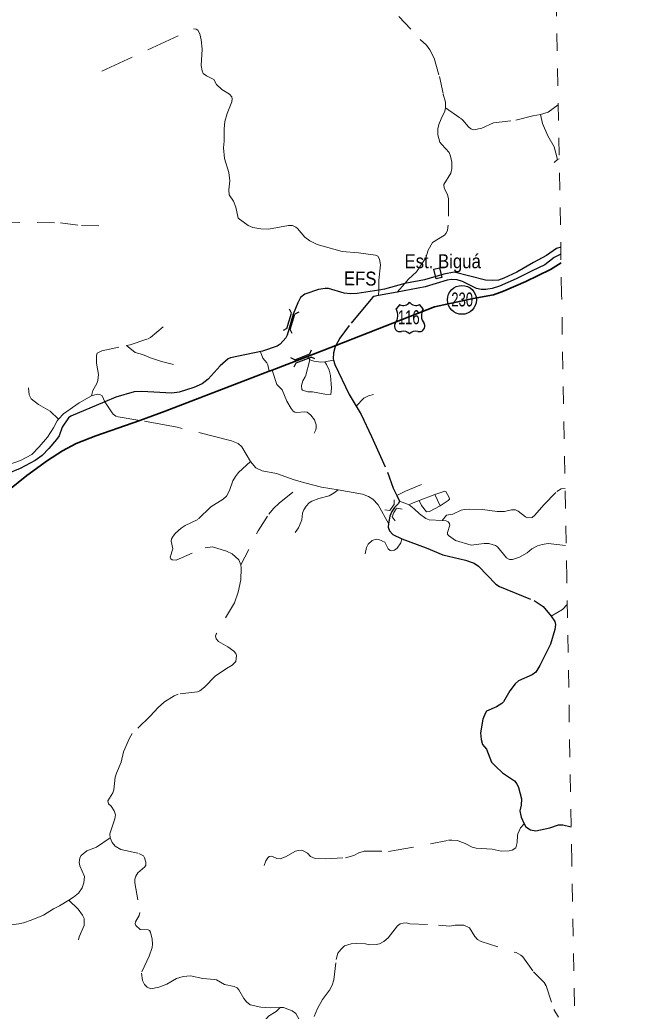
# Model space of a CAD drawing. Extents: x 220.8 to 246.7, y 7287.6 to 7315.8.
# Drawn here: x 243.16 to 246.65, y 7305.15 to 7310.84 of the extents above; entities that cross this region are included whole.
import ezdxf
from ezdxf.enums import TextEntityAlignment as Align

# ---------------------------------------------------------------- set-up
doc = ezdxf.new("R2010")
doc.units = 0
doc.header["$LTSCALE"] = 0.032
for name, pattern in [('DOTTED', [1.5, 0.3, -1.2]), ('LONG_DASHED', [7.5, 6, -1.5]), ('MEDIUM_DASHED', [4.5, 3, -1.5]), ('SHORT_DASHED', [2.7, 1.5, -1.2])]:
    doc.linetypes.add(name, pattern=pattern)
for name, color, linetype, lineweight in [('10', 7, 'Continuous', 25), ('11', 7, 'Continuous', 13), ('12', 7, 'Continuous', 25), ('13', 7, 'Continuous', 25), ('15', 7, 'Continuous', 25), ('2', 7, 'Continuous', 35), ('28', 7, 'Continuous', 25), ('35', 7, 'SHORT_DASHED', 13), ('4', 7, 'LONG_DASHED', 25), ('5', 7, 'LONG_DASHED', 13), ('6', 7, 'MEDIUM_DASHED', 13), ('7', 7, 'DOTTED', 13)]:
    doc.layers.add(name, color=color, linetype=linetype, lineweight=lineweight)
doc.layers.add('61', color=7, linetype='Continuous')

msp = doc.modelspace()

# ---------------------------------------------------------------- linework, layer by layer
at = {"layer": '10'}
for p, q in [((244.71, 7309.0644), (244.7373, 7309.1527)), ((244.7593, 7309.1644), (244.7373, 7309.1527)), ((244.6908, 7309.0703), (244.6687, 7309.0587)), ((244.7215, 7309.0424), (244.71, 7309.0644)), ((244.7359, 7308.8913), (244.7131, 7308.9014)), ((244.7332, 7308.8499), (244.7431, 7308.8727)), ((244.7431, 7308.8727), (244.8293, 7308.9061)), ((244.8522, 7308.8961), (244.8293, 7308.9061))]:
    msp.add_line(p, q, dxfattribs=at)
for points in [[(244.6908, 7309.0703), (244.7182, 7309.1586), (244.7065, 7309.1808)], [(244.7359, 7308.8913), (244.8221, 7308.9248), (244.8322, 7308.9477)]]:
    msp.add_lwpolyline(points, dxfattribs=at)
at = {"layer": '11'}
for points in [[(245.3067, 7308.0857), (245.3077, 7308.0596), (245.2986, 7308.05), (245.2811, 7308.0249), (245.2538, 7308.0278)], [(245.3536, 7308.0318), (245.3234, 7308.0384), (245.3188, 7308.0336), (245.3043, 7308.0127), (245.2949, 7307.9882), (245.3117, 7307.9649)]]:
    msp.add_lwpolyline(points, dxfattribs=at)
at = {"layer": '12'}
for p, q in [((245.3385, 7309.2082), (245.3176, 7309.1839)), ((245.4738, 7309.1841), (245.4528, 7309.2082))]:
    msp.add_line(p, q, dxfattribs=at)
for centre, radius, start, end in [((245.3593, 7309.2483), 0.0452, 242.5287, 323.4161), ((245.4319, 7309.2483), 0.0452, 216.5968, 297.4912), ((245.2544, 7309.1457), 0.0738, 320.9608, 31.1419), ((245.5368, 7309.1457), 0.0738, 148.687, 219.0536), ((245.3396, 7309.0841), 0.0316, 151.5003, 286.5066), ((245.4517, 7309.0841), 0.0316, 253.4942, 28.4996), ((245.3616, 7309.0124), 0.0433, 38.3472, 107.6219), ((245.4296, 7309.0124), 0.0433, 72.467, 141.6528)]:
    msp.add_arc(centre, radius, start, end, dxfattribs=at)
at = {"layer": '13'}
msp.add_circle((245.6962, 7309.235), 0.083, dxfattribs=at)
at = {"layer": '15'}
msp.add_lwpolyline([(246.2637, 7309.5375), (246.2398, 7309.5298), (246.1817, 7309.4896), (246.1065, 7309.4503), (246.0116, 7309.3947), (245.9373, 7309.3597), (245.9065, 7309.3486), (245.8741, 7309.346), (245.8322, 7309.3477), (245.6519, 7309.3939), (245.592, 7309.3828), (245.4818, 7309.3495), (245.369, 7309.3293), (245.2511, 7309.2965), (245.2179, 7309.2911), (245.0938, 7309.2708), (245.0562, 7309.27), (245.0195, 7309.2743), (244.9306, 7309.3007), (244.9101, 7309.3007), (244.8725, 7309.2948), (244.7939, 7309.2683), (244.7691, 7309.2478), (244.7529, 7309.2179), (244.7262, 7309.1519), (244.7011, 7309.064), (244.6933, 7309.0331), (244.6854, 7309.017), (244.652, 7308.9811), (244.6341, 7308.9683), (244.5503, 7308.9401), (244.3675, 7308.9025), (244.3538, 7308.8965), (244.3076, 7308.8555), (244.2384, 7308.7786), (244.2034, 7308.7521), (244.1572, 7308.7316), (244.0726, 7308.7051), (244.0299, 7308.6983), (243.8573, 7308.7085), (243.8146, 7308.7068), (243.7086, 7308.6761), (243.6456, 7308.6496), (243.4505, 7308.5675), (243.4368, 7308.5573), (243.4001, 7308.5043), (243.3822, 7308.4539), (243.3676, 7308.4317), (243.324, 7308.3804), (243.2847, 7308.3411), (243.2446, 7308.3112), (243.1583, 7308.265), (243.0839, 7308.236)], dxfattribs=at)
at = {"layer": '2'}
msp.add_lwpolyline([(242.9873, 7308.0568), (243.1979, 7308.2257), (243.316, 7308.311), (243.4026, 7308.3674), (243.4813, 7308.4094), (243.5941, 7308.4527), (243.8457, 7308.5424), (243.9917, 7308.5944), (244.5891, 7308.8254), (244.6053, 7308.8315), (244.7744, 7308.8953), (244.8086, 7308.9086), (244.9724, 7308.9729), (245.5386, 7309.1953), (245.7603, 7309.2426), (245.8771, 7309.2649), (245.9349, 7309.2845), (246.0634, 7309.3397), (246.2038, 7309.4092), (246.2653, 7309.4486)], dxfattribs=at)
at = {"layer": '28'}
msp.add_lwpolyline([(245.5668, 7309.4186), (245.5803, 7309.3632), (245.5473, 7309.3552), (245.5338, 7309.4106)], close=True, dxfattribs=at)
at = {"layer": '35'}
msp.add_lwpolyline([(246.6507, 7288.0853), (246.6212, 7289.7146), (246.5917, 7291.3439), (246.5622, 7292.9732), (246.5328, 7294.6024), (246.5034, 7296.2317), (246.4739, 7297.861), (246.4446, 7299.4903), (246.4152, 7301.1196), (246.3858, 7302.7489), (246.3565, 7304.3782), (246.3272, 7306.0075), (246.2979, 7307.6367), (246.2685, 7309.266), (246.2393, 7310.8953), (246.21, 7312.5246), (246.1808, 7314.1539), (246.1516, 7315.7832)], dxfattribs=at)
at = {"layer": '4'}
msp.add_lwpolyline([(246.2644, 7309.4984), (246.2261, 7309.4787), (246.1726, 7309.436), (246.0998, 7309.4011), (246.007, 7309.3567), (245.9117, 7309.3131), (245.8706, 7309.3003), (245.8325, 7309.2937), (245.8063, 7309.2937), (245.78, 7309.3003), (245.7, 7309.3397), (245.6685, 7309.3502), (245.637, 7309.3515), (245.6108, 7309.3488), (245.4848, 7309.3095), (245.325, 7309.2795), (245.2171, 7309.2593), (245.1909, 7309.2544), (245.1817, 7309.2491), (245.0492, 7309.0877), (244.9941, 7309.0143), (244.9724, 7308.9729), (244.9652, 7308.9592), (244.9587, 7308.9303), (244.9561, 7308.8962), (244.9582, 7308.8884), (244.9652, 7308.8634), (245.0479, 7308.6915), (245.0882, 7308.6245), (245.1174, 7308.576), (245.1765, 7308.4501), (245.2683, 7308.2441), (245.3011, 7308.1522), (245.322, 7308.1114), (245.3366, 7308.0774), (245.3313, 7308.0656), (245.3087, 7308.0418), (245.2927, 7308.0188), (245.2828, 7307.9928), (245.2737, 7307.9488), (245.2723, 7307.9292), (245.2801, 7307.9069), (245.2998, 7307.8859), (245.3513, 7307.8615), (245.4914, 7307.8098), (245.5858, 7307.7704), (245.7157, 7307.7389), (245.7656, 7307.7219), (245.7918, 7307.7048), (245.8916, 7307.6012), (245.9125, 7307.5867), (246.1107, 7307.5067), (246.1632, 7307.4726), (246.2088, 7307.4174), (246.2288, 7307.3873), (246.234, 7307.3689), (246.2301, 7307.3401), (246.2051, 7307.2561), (246.1435, 7307.1341), (246.1199, 7307.096), (246.1002, 7307.0803), (246.0214, 7307.0449), (246.0018, 7307.0291), (245.9716, 7306.9884), (245.9349, 7306.9255), (245.9244, 7306.915), (245.8955, 7306.8966), (245.8378, 7306.8704), (245.8299, 7306.8585), (245.8168, 7306.8257), (245.8023, 7306.7457), (245.8063, 7306.7077), (245.8141, 7306.6801), (245.8364, 7306.6525), (245.8666, 7306.5778), (245.8889, 7306.5541), (245.9293, 7306.5172), (245.9978, 7306.4702), (246.0115, 7306.4533), (246.0201, 7306.4321), (246.0385, 7306.3665), (246.0372, 7306.3311), (246.0293, 7306.2983), (246.0359, 7306.2616), (246.0541, 7306.2228), (246.0634, 7306.2064), (246.0897, 7306.1881), (246.1212, 7306.1828), (246.2012, 7306.2012), (246.2511, 7306.2169), (246.276, 7306.2169), (246.3236, 7306.2065)], dxfattribs=at)
at = {"layer": '5'}
for points in [[(243.6274, 7310.5486), (244.1537, 7310.7934), (244.1691, 7310.7912), (244.179, 7310.7846), (244.1901, 7310.7647), (244.1989, 7310.7294), (244.2033, 7310.6765), (244.1989, 7310.5827), (244.2033, 7310.5518), (244.2099, 7310.5353), (244.2287, 7310.522), (244.2706, 7310.5022), (244.2871, 7310.4724), (244.318, 7310.4437), (244.3611, 7310.4172), (244.3743, 7310.4029), (244.3765, 7310.3897), (244.3743, 7310.3742), (244.3478, 7310.3058), (244.3346, 7310.2606), (244.3302, 7310.2187), (244.3313, 7310.1481), (244.3258, 7310.1084), (244.3324, 7310.0477), (244.3577, 7309.9672), (244.3622, 7309.9186), (244.3566, 7309.8668), (244.36, 7309.8392), (244.3842, 7309.8017), (244.3975, 7309.7686), (244.4107, 7309.7046), (244.4681, 7309.6616), (244.4945, 7309.6517), (244.542, 7309.6429), (244.585, 7309.6407), (244.7008, 7309.6627), (244.7229, 7309.6616), (244.7427, 7309.6528), (244.7515, 7309.6451), (244.7935, 7309.5954), (244.8221, 7309.5745), (244.8641, 7309.5524), (245.0075, 7309.5127), (245.1023, 7309.505), (245.1994, 7309.4929), (245.2126, 7309.4862), (245.2226, 7309.4697), (245.2281, 7309.4366), (245.2193, 7309.3483), (245.2179, 7309.2911), (245.2171, 7309.2593)], [(245.2737, 7307.9488), (245.215, 7308.0575), (245.1848, 7308.0897), (245.1587, 7308.1058), (245.1245, 7308.1178), (244.9847, 7308.1423), (244.8891, 7308.1591), (244.7942, 7308.184), (244.7321, 7308.2003), (244.6305, 7308.2375), (244.548, 7308.2526), (244.5118, 7308.2697), (244.4822, 7308.3063), (244.4314, 7308.3905), (244.4102, 7308.4086), (244.372, 7308.4257), (244.0612, 7308.5031), (243.8457, 7308.5424), (243.7211, 7308.5625), (243.7081, 7308.5675), (243.694, 7308.5776), (243.6839, 7308.5906), (243.6456, 7308.6496), (243.6296, 7308.6832), (243.6165, 7308.6902), (243.6011, 7308.6925), (243.5689, 7308.6832), (243.4978, 7308.6429), (243.4076, 7308.5799), (243.3796, 7308.5492), (243.3711, 7308.5393), (243.351, 7308.5001), (243.3168, 7308.4458), (243.2685, 7308.3905), (243.2252, 7308.3472), (243.1608, 7308.311), (242.9743, 7308.2489)]]:
    msp.add_lwpolyline(points, dxfattribs=at)
at = {"layer": '6'}
for p, q in [((245.3366, 7308.0774), (245.3921, 7308.0561)), ((245.4512, 7308.0826), (245.5402, 7308.1162)), ((245.5402, 7308.1162), (245.5718, 7308.0517))]:
    msp.add_line(p, q, dxfattribs=at)
for points in [[(245.3344, 7310.8639), (245.4563, 7310.7321), (245.4927, 7310.698), (245.5109, 7310.673), (245.5358, 7310.6238), (245.5669, 7310.5193), (245.5881, 7310.4178), (245.601, 7310.3723), (245.6018, 7310.3384), (245.5987, 7310.3193), (245.576, 7310.2754), (245.5639, 7310.2421), (245.5571, 7310.2178), (245.5571, 7310.1837), (245.5699, 7310.1421), (245.5798, 7310.1277), (245.6222, 7310.083), (245.6313, 7310.0618), (245.6389, 7310.0262), (245.6389, 7309.9906), (245.632, 7309.9626), (245.5919, 7309.899), (245.5949, 7309.8777), (245.6131, 7309.8399), (245.6192, 7309.8156), (245.6176, 7309.6642), (245.6123, 7309.6361), (245.6055, 7309.6187), (245.5957, 7309.6073), (245.5268, 7309.5657), (245.5025, 7309.5202), (245.4881, 7309.4763), (245.4344, 7309.3968), (245.3897, 7309.3544), (245.369, 7309.3293), (245.325, 7309.2795)], [(244.4822, 7308.3063), (244.4127, 7308.2425), (244.3959, 7308.2195), (244.3806, 7308.1951), (244.3607, 7308.14), (244.3431, 7308.1063), (244.3255, 7308.0903), (244.2544, 7308.0459), (244.1794, 7307.9733), (244.106, 7307.9388), (244.0838, 7307.9235), (244.0509, 7307.8937), (244.0379, 7307.8777), (244.0288, 7307.8608), (244.0265, 7307.8486), (244.0364, 7307.805), (244.0204, 7307.756), (244.0242, 7307.7461), (244.0326, 7307.7415), (244.054, 7307.7392), (244.2207, 7307.8103), (244.2628, 7307.8149), (244.3439, 7307.7905), (244.376, 7307.7752), (244.4146, 7307.7411), (244.4259, 7307.7114), (244.4285, 7307.6924), (244.4257, 7307.6253), (244.4104, 7307.5549), (244.389, 7307.4929), (244.2842, 7307.314), (244.2812, 7307.304), (244.285, 7307.2864), (244.2988, 7307.2719), (244.3508, 7307.2413), (244.386, 7307.2161), (244.3982, 7307.2023), (244.402, 7307.1916), (244.3967, 7307.1572), (244.376, 7307.135), (244.3431, 7307.1159), (244.2796, 7307.0715), (244.2184, 7307.0088), (244.1901, 7306.9874), (244.1771, 7306.9828), (244.0655, 7306.9683), (244.0425, 7306.9598), (243.9875, 7306.9247), (243.9515, 7306.8925), (243.9064, 7306.8421), (243.8016, 7306.7419), (243.7863, 7306.7159), (243.7527, 7306.6378), (243.7397, 7306.5774), (243.7121, 7306.5155), (243.7052, 7306.4925), (243.6961, 7306.4183), (243.6907, 7306.4023), (243.6624, 7306.3548), (243.6655, 7306.3388), (243.6815, 7306.325), (243.6991, 7306.2982), (243.706, 7306.2761), (243.7022, 7306.2531), (243.6731, 7306.1667), (243.6757, 7306.1433), (243.6869, 7306.117), (243.7052, 7306.0948), (243.7374, 7306.0764), (243.8414, 7306.0527), (243.8666, 7306.0397), (243.8735, 7306.0283), (243.8804, 7306.0023), (243.8812, 7305.9862), (243.8758, 7305.977), (243.8345, 7305.9411), (243.8223, 7305.9227), (243.8184, 7305.9059), (243.8184, 7305.8845), (243.846, 7305.7139), (243.8421, 7305.6971), (243.8215, 7305.6611), (243.8192, 7305.6497), (243.8238, 7305.6397), (243.849, 7305.616), (243.8949, 7305.6137), (243.901, 7305.6107), (243.9079, 7305.5999), (243.9171, 7305.5609), (243.9194, 7305.5326), (243.9171, 7305.5128), (243.8995, 7305.4638), (243.8551, 7305.3651), (243.862, 7305.3238), (243.8735, 7305.3009), (243.888, 7305.2841), (243.9102, 7305.2749), (243.9561, 7305.2848), (244.0012, 7305.3017), (244.0563, 7305.3338), (244.0945, 7305.3468)], [(245.322, 7308.1114), (245.3721, 7308.1357), (245.4892, 7308.1831)], [(245.5402, 7308.1162), (245.5976, 7308.1357), (245.6034, 7308.1336), (245.6235, 7308.0998), (245.6242, 7308.089), (245.617, 7308.0812), (245.5718, 7308.0517)], [(245.3921, 7308.0561), (245.4059, 7308.0654), (245.4512, 7308.0826)], [(245.5718, 7308.0517), (245.5093, 7308.018), (245.4935, 7308.0172), (245.4648, 7308.0539), (245.4512, 7308.0826)], [(245.3921, 7308.0561), (245.4217, 7308.0338), (245.4526, 7308.0043), (245.4892, 7307.9785), (245.5086, 7307.9706), (245.5817, 7307.9677), (245.6062, 7307.9655), (245.617, 7307.9591), (245.6249, 7307.9497), (245.6271, 7307.9397), (245.6127, 7307.898), (245.6141, 7307.888), (245.6192, 7307.8808), (245.6586, 7307.8528), (245.7484, 7307.8255), (245.8238, 7307.8341), (245.8511, 7307.8341), (245.8884, 7307.8234), (245.8999, 7307.8162), (245.9523, 7307.7516), (245.9688, 7307.7437), (245.9868, 7307.7422), (246.027, 7307.7566), (246.0701, 7307.7817), (246.0967, 7307.8047), (246.1304, 7307.8219), (246.1577, 7307.8291), (246.1907, 7307.8341), (246.2945, 7307.8234)], [(244.8472, 7305.1158), (244.867, 7305.1617), (244.8961, 7305.2129), (244.9351, 7305.2672), (244.9504, 7305.2955), (244.9596, 7305.3261), (244.9741, 7305.4447), (244.9841, 7305.4799), (245.0017, 7305.5036), (245.0223, 7305.5219), (245.0598, 7305.5334), (245.0881, 7305.5357), (245.1431, 7305.5342), (245.1661, 7305.5288), (245.2036, 7305.5296), (245.2235, 7305.5342), (245.2479, 7305.5464), (245.2724, 7305.5686), (245.3259, 7305.6374), (245.342, 7305.6489), (245.3588, 7305.6535), (245.3764, 7305.6542), (245.3978, 7305.6489), (245.5623, 7305.6412), (245.6258, 7305.6344), (245.6564, 7305.6405), (245.7061, 7305.6412), (245.739, 7305.626), (245.7703, 7305.5755), (245.7864, 7305.5586), (245.8063, 7305.5472), (246.0067, 7305.4837), (246.035, 7305.4692), (246.0449, 7305.46), (246.1069, 7305.3728), (246.168, 7305.3116), (246.1795, 7305.2932), (246.2246, 7305.1571), (246.2514, 7305.112)], [(244.0945, 7305.3468), (244.1381, 7305.3498), (244.2085, 7305.3353), (244.2743, 7305.3292), (244.2873, 7305.3269), (244.3316, 7305.2994), (244.3875, 7305.2887), (244.4051, 7305.2802), (244.415, 7305.2695), (244.4433, 7305.2198), (244.4594, 7305.1999), (244.48, 7305.1831), (244.5404, 7305.1693), (244.5948, 7305.1655), (244.653, 7305.1673), (244.6712, 7305.1678), (244.7217, 7305.1487), (244.7416, 7305.1326), (244.7722, 7305.0776), (244.7913, 7305.0592), (244.8112, 7305.0462), (244.8349, 7305.0363)]]:
    msp.add_lwpolyline(points, dxfattribs=at)
at = {"layer": '7'}
for p, q in [((246.2452, 7310.0413), (246.2253, 7310.0249)), ((246.2452, 7310.0413), (246.2545, 7310.0457)), ((244.8086, 7308.9086), (244.8225, 7308.8903)), ((244.9085, 7308.8784), (244.9582, 7308.8884))]:
    msp.add_line(p, q, dxfattribs=at)
for points in [[(246.1477, 7310.3013), (246.192, 7310.3147), (246.249, 7310.3569)], [(245.6018, 7310.3384), (245.6884, 7310.2786), (245.7019, 7310.2671), (245.7329, 7310.2297), (245.7469, 7310.2185), (245.7639, 7310.2127), (245.8102, 7310.2223), (245.878, 7310.2518), (246.0063, 7310.2677), (246.1044, 7310.2933), (246.1477, 7310.3013)], [(246.1477, 7310.3013), (246.1584, 7310.2493), (246.19, 7310.1786), (246.225, 7310.1148), (246.2452, 7310.0413)], [(242.6173, 7309.9445), (242.8268, 7309.7632), (242.8603, 7309.7372), (242.9081, 7309.7149), (242.9788, 7309.6952), (243.0314, 7309.6835), (243.057, 7309.6814), (243.3914, 7309.6776), (243.5104, 7309.6628), (243.6237, 7309.6596)], [(243.7702, 7308.9725), (243.7909, 7308.9764), (243.891, 7309.0101), (243.907, 7309.0187), (243.9805, 7309.08)], [(243.5689, 7308.6832), (243.5762, 7308.7144), (243.5993, 7308.7536), (243.6053, 7308.7707), (243.6083, 7308.8064), (243.5978, 7308.8708), (243.5968, 7308.9151), (243.6008, 7308.9281), (243.628, 7308.9422), (243.7702, 7308.9725)], [(243.7702, 7308.9725), (243.8201, 7308.9332), (243.8623, 7308.9216), (243.907, 7308.9015), (243.9714, 7308.8804), (244.0388, 7308.8633)], [(244.5392, 7308.9355), (244.5535, 7308.9007), (244.5757, 7308.8733), (244.5816, 7308.8616), (244.5891, 7308.8254)], [(244.8225, 7308.8903), (244.7966, 7308.793), (244.7819, 7308.7695), (244.7751, 7308.7433), (244.776, 7308.7203), (244.7807, 7308.7161), (244.8107, 7308.7058), (244.8374, 7308.7058), (244.9096, 7308.6922), (244.9438, 7308.6908), (244.9471, 7308.7274), (244.9405, 7308.8), (244.933, 7308.8305), (244.9185, 7308.8642), (244.9085, 7308.8784)], [(244.8225, 7308.8903), (244.8446, 7308.8829), (244.8852, 7308.8774), (244.9085, 7308.8784)], [(244.6053, 7308.8315), (244.6325, 7308.7485), (244.6627, 7308.7174), (244.6913, 7308.6535), (244.7149, 7308.6107), (244.7266, 7308.5955), (244.7363, 7308.5892), (244.7455, 7308.5875), (244.7947, 7308.5917), (244.8065, 7308.5888), (244.8283, 7308.5728), (244.8498, 7308.5447), (244.859, 7308.5161), (244.8594, 7308.5018), (244.8573, 7308.4884), (244.8472, 7308.4682)], [(243.3796, 7308.5492), (243.3308, 7308.5956), (243.264, 7308.6345), (243.2219, 7308.6671), (243.211, 7308.6885), (243.2067, 7308.7301)], [(245.0882, 7308.6245), (245.1325, 7308.6697), (245.1593, 7308.6839), (245.1877, 7308.6902)], [(244.4259, 7307.7114), (244.526, 7307.9069), (244.5863, 7308.0032), (244.614, 7308.036), (244.6473, 7308.0668), (244.7942, 7308.184)], [(244.7385, 7307.8989), (244.7572, 7307.9252), (244.7765, 7307.9717), (244.7812, 7308.0094), (244.7879, 7308.0275), (244.8006, 7308.0485), (244.8193, 7308.0686), (244.8347, 7308.0786), (244.8744, 7308.0929), (244.9335, 7308.1096), (244.9619, 7308.125), (244.9847, 7308.1423)], [(245.5817, 7307.9677), (245.6082, 7307.998), (245.6431, 7308.0031), (245.6925, 7308.026), (245.7117, 7308.0308), (245.7403, 7308.0329), (245.8147, 7308.0302), (245.899, 7308.0194), (245.9409, 7308.0178), (245.9806, 7308.0281), (246.0029, 7308.0287), (246.0189, 7308.0215), (246.0604, 7307.9874), (246.0725, 7307.9832), (246.0993, 7307.9847), (246.1152, 7307.9977), (246.1661, 7308.0564), (246.2411, 7308.1344), (246.2658, 7308.1488), (246.2886, 7308.1509)], [(245.1408, 7307.7759), (245.1485, 7307.8116), (245.1575, 7307.8314), (245.1801, 7307.8527), (245.2058, 7307.859), (245.2189, 7307.8572), (245.2532, 7307.8432), (245.2717, 7307.8044), (245.2834, 7307.7944), (245.2938, 7307.7926), (245.3096, 7307.7967), (245.3236, 7307.8075), (245.3448, 7307.8378), (245.3513, 7307.8615)], [(246.2088, 7307.4174), (246.2737, 7307.4561), (246.3006, 7307.4842)], [(244.5598, 7305.9846), (244.5703, 7306.0109), (244.5808, 7306.0285), (244.5893, 7306.0348), (244.604, 7306.0376), (244.6335, 7306.0243), (244.6528, 7306.0222), (244.6833, 7306.0341), (244.7395, 7306.0657), (244.756, 7306.0703), (244.777, 7306.0713), (244.7841, 7306.0685), (244.8083, 7306.0552), (244.8265, 7306.0352), (244.8539, 7306.025), (244.9118, 7306.0232), (245.0283, 7306.0278), (245.0757, 7306.0415), (245.1041, 7306.0559), (245.1354, 7306.0664), (245.2747, 7306.0653), (245.3193, 7306.0713), (245.6183, 7306.1289), (245.6383, 7306.1303), (245.671, 7306.1268), (245.6836, 7306.1226), (245.7145, 7306.111), (245.7545, 7306.0903), (245.7773, 7306.0836), (245.8693, 7306.0776), (245.9205, 7306.0671), (245.9676, 7306.0675), (245.9844, 7306.072), (246.0058, 7306.0864), (246.0136, 7306.1166), (246.0146, 7306.1563), (246.0174, 7306.1664), (246.0332, 7306.1998), (246.0541, 7306.2228)], [(243.439, 7305.7847), (243.466, 7305.8012), (243.4933, 7305.8248), (243.5151, 7305.8553), (243.5251, 7305.8839), (243.5282, 7305.9211), (243.5024, 7305.982), (243.4978, 7306.0006), (243.5015, 7306.0278), (243.5101, 7306.0423), (243.541, 7306.0678), (243.5982, 7306.0896), (243.6757, 7306.1433)], [(242.7254, 7305.5233), (242.745, 7305.5356), (242.7749, 7305.5478), (242.8181, 7305.5587), (242.8984, 7305.5978), (242.9407, 7305.6146), (243.0024, 7305.6296), (243.0551, 7305.6382), (243.1504, 7305.6482), (243.1781, 7305.6541), (243.2226, 7305.67), (243.2939, 7305.6991), (243.3502, 7305.7354), (243.3852, 7305.7522), (243.439, 7305.7847)], [(243.439, 7305.7847), (243.4925, 7305.7327), (243.5169, 7305.6993), (243.5259, 7305.6801), (243.5259, 7305.6388), (243.4981, 7305.5746), (243.4932, 7305.5562)], [(244.4549, 7304.8601), (244.4708, 7304.8956), (244.5039, 7304.9301), (244.523, 7304.9879), (244.5365, 7305.02), (244.5514, 7305.0443), (244.5622, 7305.0872), (244.5678, 7305.0974), (244.5859, 7305.1184), (244.6298, 7305.145), (244.653, 7305.1673)]]:
    msp.add_lwpolyline(points, dxfattribs=at)

# ---------------------------------------------------------------- texts
at = {"layer": '61', "width": 0.9}
msp.add_text('Est. Biguá', height=0.08, dxfattribs=at).set_placement((245.3661, 7309.417))
msp.add_text('EFS', height=0.08, rotation=359.404, dxfattribs=at).set_placement((245.1114, 7309.3179), align=Align.CENTER)
at = {"layer": '61', "width": 0.7}
for s, p in [('230', (245.6974, 7309.1973)), ('116', (245.3908, 7309.0953))]:
    msp.add_text(s, height=0.08, dxfattribs=at).set_placement(p, align=Align.CENTER)

doc.saveas('drawing.dxf')
